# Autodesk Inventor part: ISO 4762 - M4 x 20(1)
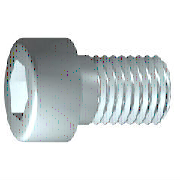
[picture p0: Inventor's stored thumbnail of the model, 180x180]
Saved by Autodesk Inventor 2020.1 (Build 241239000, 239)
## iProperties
Created: 2019-01
Part Number: ISO 4762 - M4 x 20(1)
Material: Edelstahl, 440C
Description: Innensechskantschraube
Document SubType Name: Modeling
Standard: ISO 4762
Designer: lutzd
Standard Revision: Fourth edition 2004-03-01
Standards Organization: ISO
Language: de-DE
Size Designation: M4 x 20
Categories: <MemberInstance><Categories><Category DisplayName="Verbindungselemente" InternalName="e4da775c-781d-43d5-af7c-5136215cf5a6" Mnemonic="FSTN"><Category DisplayNam
Mass: 2.98249 g
Surface Area: 4.31384 cm^2
Volume: 0.384837 cm^3
Density: 7.75 g/cm^3
Appearance: Halbpoliert
IsCustomPart: 0
Author: lutzd
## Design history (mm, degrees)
workplane "Work Plane1"
fillet "Fillet2" dims "d30" = 0.1 (= R)
sketch "Skizze1"
  geometry: L1 (-1, 0)-(20, 0); L2 (20, 0)-(20, 2); L3 (20, 2)-(1.75, 2); L4 (1.75, 2)-(1.32, 2); L5 (1.32, 2)-(0, 2); L6 (0, 2)-(0, 3.5); L7 (0, 3.5)-(-4, 3.5); L8 (-4, 3.5)-(-4, 1.732); L9 (-4, 1.732)-(-2, 1.732); L10 (-2, 1.732)-(-1, 0); L11 (-8.8, 0)-(24.8, 0) reference; L12 (0, -0.7)-(0, 4.2) reference; L13 (1.75, 2)-(0, 2)
  constraints: 22 end point, 6 parallel, 2 collinear, 2 perpendicular, 1 horizontal, 1 point on line
  dimensions: "d1" = 18.25 distance from line of L3.end L2 (= GEL); "d2" = 0.42952 distance of L4.end L3.end (computed from GAL); "d3" = 4 distance between parallel lines of L8 L6 (= KOH); "d4" = 2 distance of L8.end L9.end (= INTI); "d5" = 60 deg angle of L10 L1; "d6" = 4 diameter of L3 L1 (= GD); "d7" = 4 diameter of L5 L1 (= BDM); "d8" = 3.4641 diameter of L9 L1 (= 1.1547 x SW); "d9" = 7 diameter of L7 L1 (= KOD); "d26" = 20 distance between parallel lines of L12 L2 (= NLG)
revolve "Körper" sketch "Skizze1" stored, may be unused: angle "d10" = 90 deg
sketch "Skizze2"
  geometry: L1 (0, -4.9)-(0, 4.9) reference; L2 (-4.9, 0)-(4.9, 0) reference; L3 (1.732, 0)-(0.866, -1.5); L4 (0.866, -1.5)-(-0.866, -1.5); L5 (-0.866, -1.5)-(-1.732, 0); L6 (-1.732, 0)-(-0.866, 1.5); L7 (-0.866, 1.5)-(0.866, 1.5); L8 (0.866, 1.5)-(1.732, 0); 2 further points
  constraints: 12 end point, 1 coincident, 1 horizontal alignment, 1 point on line, 12 other
extrude "Loch" join sketch "Skizze2" stored distance "d11" = 10; taper "d12" = 0 deg
body "Solid1"
fillet "Rundung1" dims "d17" = 0.4 (= RR)
feature "Gewinde" dims "d13" = 18.25 (= GEL), "d14" = 0
chamfer "Fase1" distance "d15" = 0.42941 (= -0.5 x SPD + 0.5 x GD); stored, may be unused: second distance "d16" = 0.42941 (= GUL), angle "d27" = 45 deg
other parameters: "GD" = 4 [user parameter; used in 2 equation terms], "NLG" = 20 [user parameter; used in 1 equation term], "GEL" = 18.25 [user parameter; used in 2 equation terms], "KOD" = 7 [user parameter; used in 1 equation term], "KOH" = 4 [user parameter; used in 1 equation term], "INTI" = 2 [user parameter; used in 1 equation term], "GAL" = 0.42941 (= 0.61345 x PTC) [user parameter; used in 1 equation term], "GUL" = 0.42941 (= 0.61345 x PTC) [user parameter; used in 1 equation term], "BDM" = 4 (= NND) [user parameter; used in 1 equation term], "SW" = 3 [user parameter; used in 2 equation terms], "RR" = 0.4 [user parameter; used in 1 equation term], "SPD" = 3.14117 (= NND - 1.2269 x PTC) [user parameter; used in 1 equation term], "d19" = 0, "d28" = 0, "d29" = 0, "R" = 0.1 [user parameter; used in 1 equation term], "TOA" = 30 deg [user parameter], "GD1" = 3.14117 (= THREADDIA - 1.2269 x PTC) [user parameter], "THREADDIA" = 4 [user parameter; used in 1 equation term], "FAWI" = 45 deg [user parameter], "TPU" = 14.28571 (computed from PTC) [user parameter], "PTC" = 0.7 [user parameter; used in 5 equation terms], "NND" = 4 [user parameter; used in 2 equation terms], "E0" = 3.465 (= 1.155 x SW) [user parameter]
